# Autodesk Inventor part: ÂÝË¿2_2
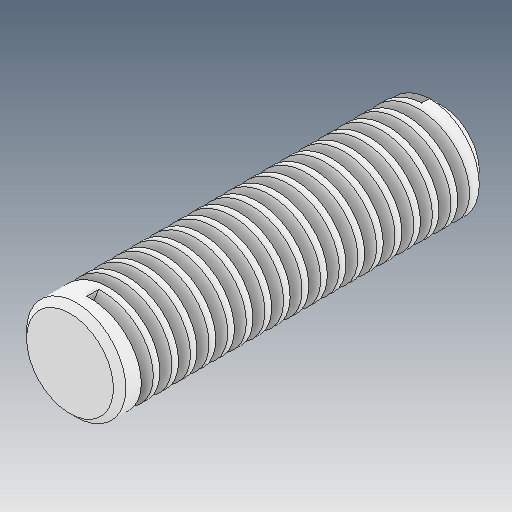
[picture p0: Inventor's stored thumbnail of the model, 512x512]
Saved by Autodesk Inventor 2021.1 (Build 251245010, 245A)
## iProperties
Created: 2021-05
Part Number: ÂÝË¿2_2
Material: Ogólny
Document SubType Name: Modeling
Designer: user
Density: 1 g/cm^3
Appearance: Domyślna
Author: user
Revision Number: ÈÎºÎ
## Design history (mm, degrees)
feature "ÊäÈë1"
node "Bryła1"
